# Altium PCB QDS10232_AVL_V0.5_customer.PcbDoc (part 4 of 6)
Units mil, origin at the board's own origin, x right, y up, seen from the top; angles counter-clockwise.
Board outline 3500 x 3799 mil, 6 copper layers (Top Layer, GND, INT1, PWR1, PWR2, Bottom Layer), stack 78.834 mil thick; 254 components, 204 nets, 7039 pads, 595 vias.
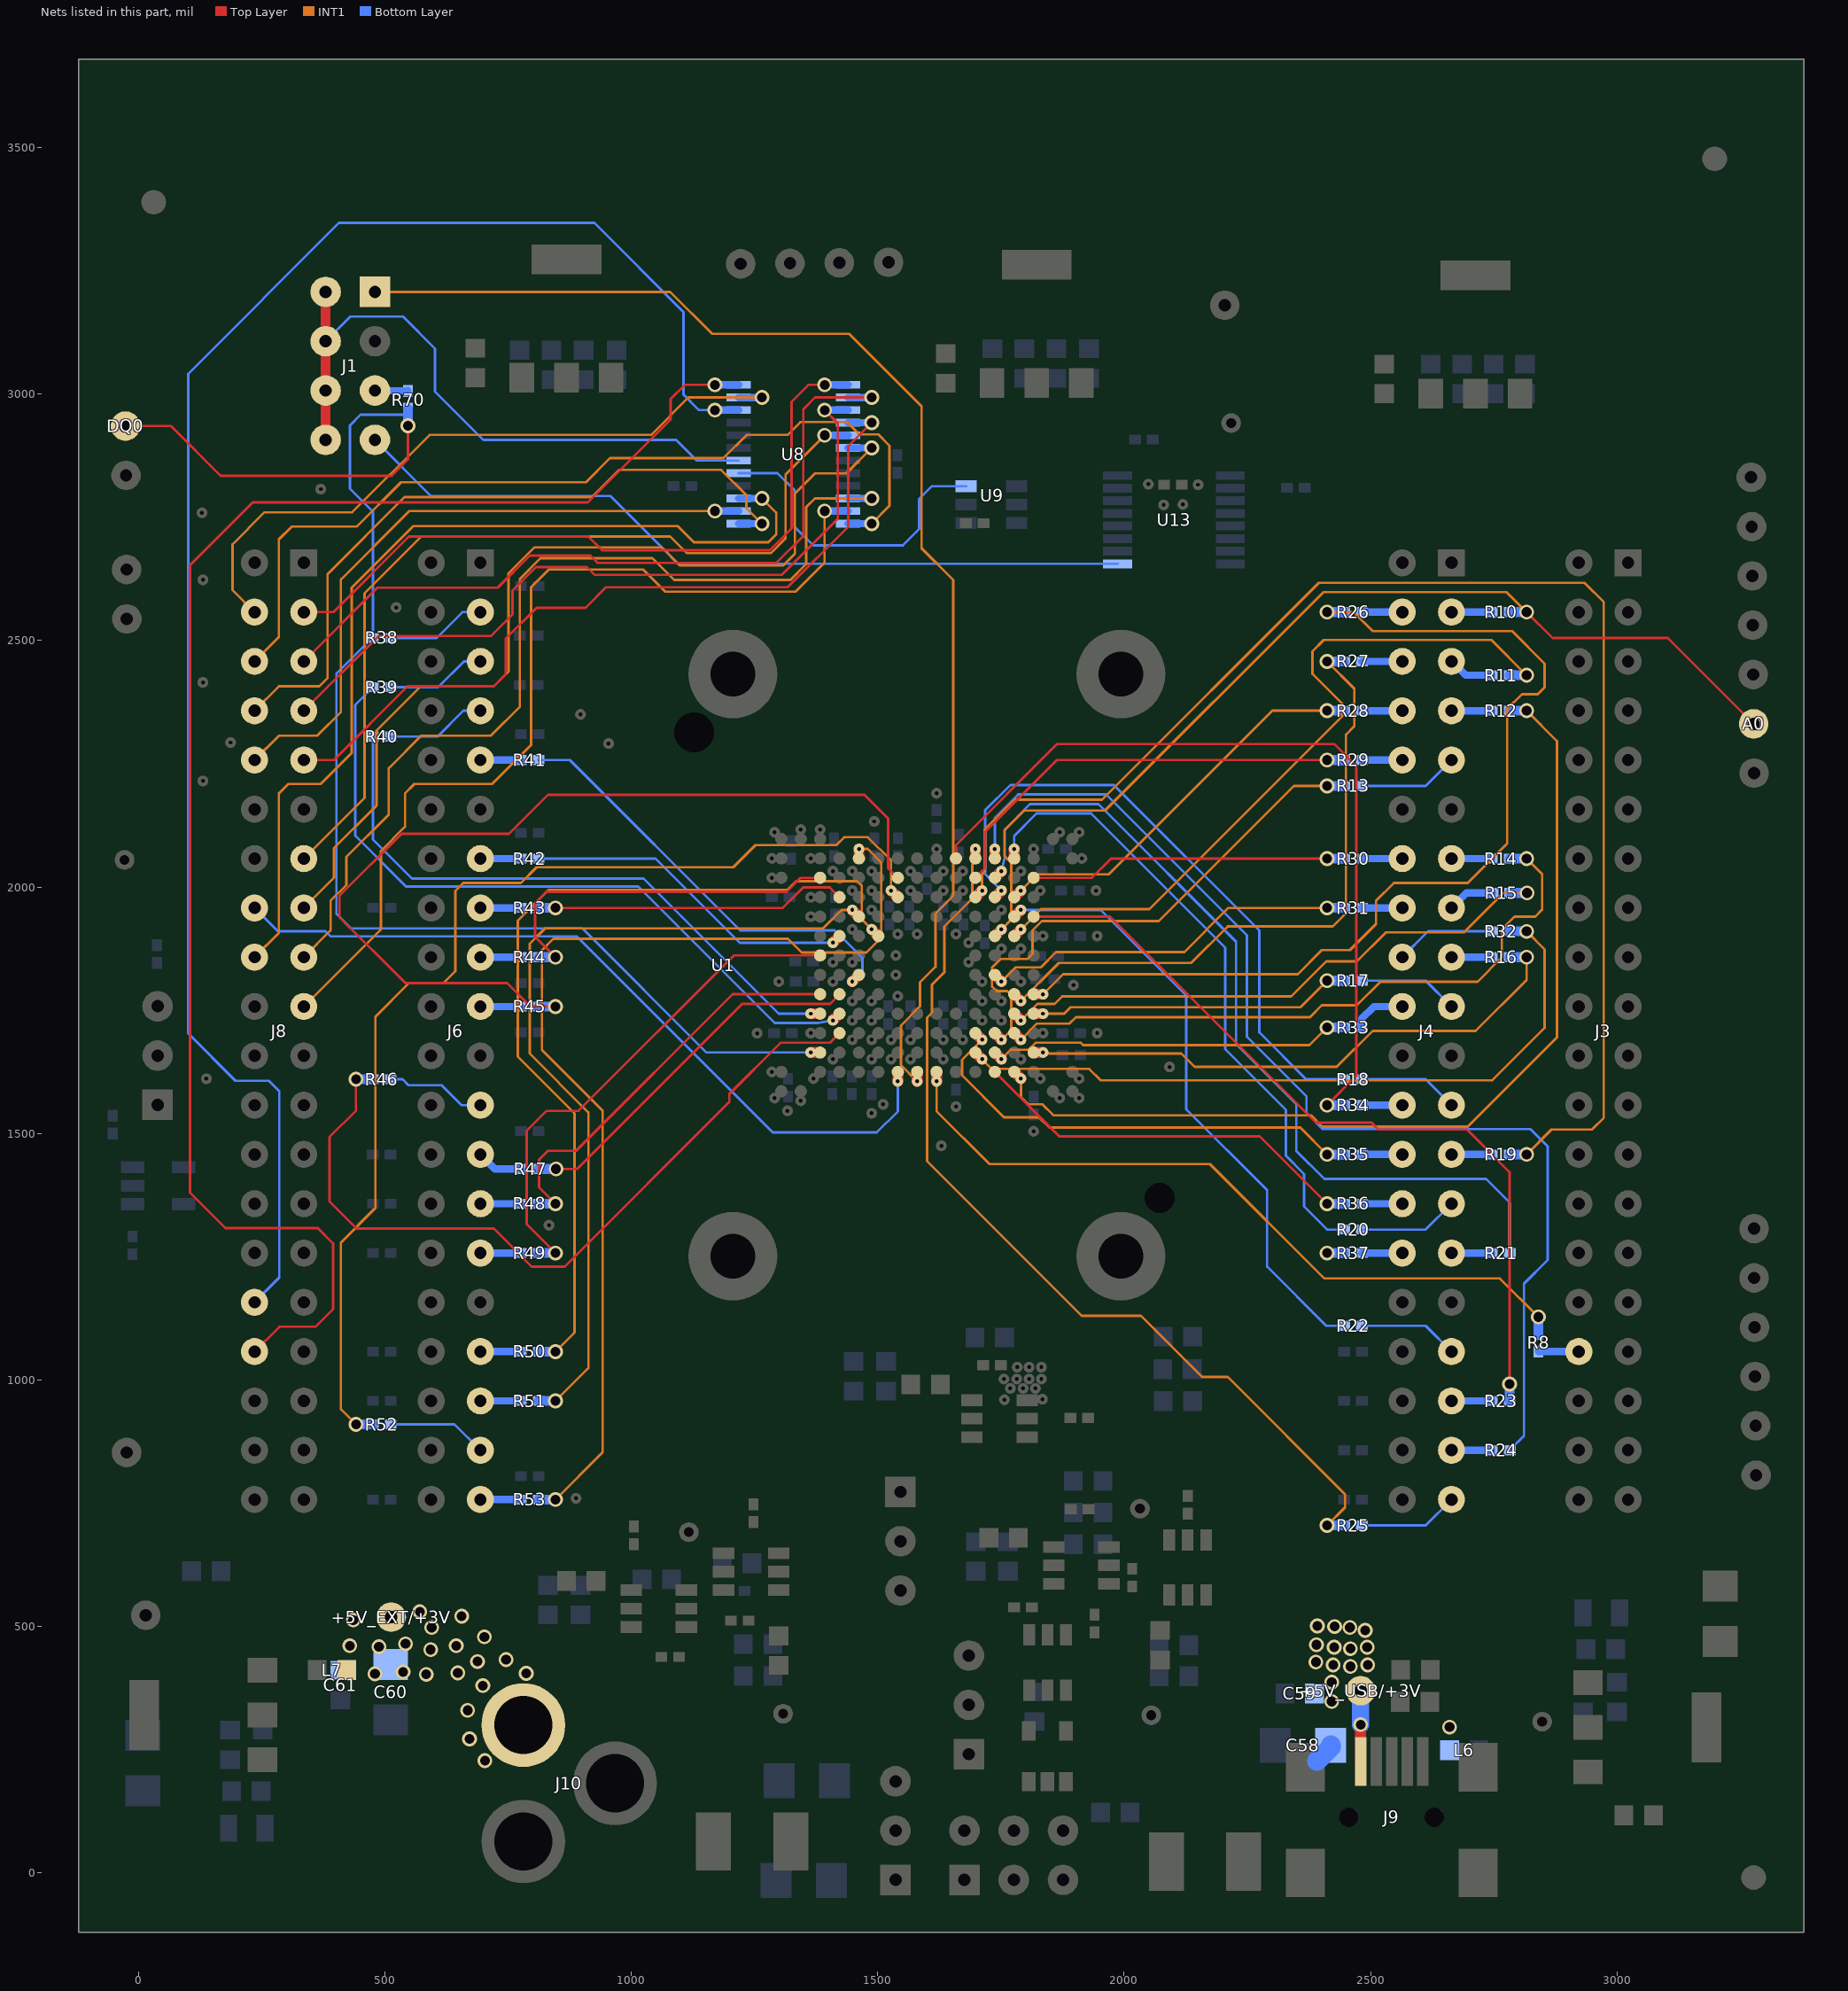
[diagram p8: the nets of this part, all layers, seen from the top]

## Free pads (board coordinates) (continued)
  round 1.28 on Bottom Overlay: ""(2911.56,3465.77) ""(2911.56,3465.77) ""(2911.56,3466.03) ""(2911.56,3467.05) ""(2911.56,3467.37) ""(2911.56,3467.37) ""(2911.56,3465.77) ""(2911.56,3465.77) ""(2911.56,3466.03) ""(2911.56,3467.05) ""(2911.56,3467.37) ""(2911.56,3467.37) ""(2911.98,3468.08) ""(2911.98,3468.08) ""(2912.01,3465) ""(2912.01,3465) ""(2912.59,3469.11) ""(2912.59,3469.11) ""(2912.59,3463.97) ""(2912.59,3463.97) ""(2912.66,3463.86) ""(2912.66,3463.86) ""(2912.66,3463.86) ""(2912.66,3463.86) ""(2913.19,3470.14) ""(2913.19,3470.14) ""(2913.36,3462.94) ""(2913.36,3462.94) ""(2913.79,3471.16) ""(2913.79,3471.16) ""(2914.15,3461.92) ""(2914.15,3461.92) ""(2914.4,3472.19) ""(2914.4,3472.19) ""(2914.93,3460.89) ""(2914.93,3460.89) ""(2915,3473.22) ""(2915,3473.22) ""(2915.16,3534.93) ""(2915.16,3534.93) ""(2915.16,3534.93) ""(2915.16,3534.93) ""(2915.17,3534.88) ""(2915.17,3534.88) ""(2915.25,3535.91) ""(2915.25,3535.91) ""(2915.28,3533.85) ""(2915.28,3533.85) ""(2915.35,3536.93) ""(2915.35,3536.93) ""(2915.39,3532.82) ""(2915.39,3532.82) ""(2915.44,3537.96) ""(2915.45,3537.96) ""(2915.5,3531.8) ""(2915.5,3531.8) ""(2915.54,3538.99) ""(2915.54,3538.99) ""(2915.6,3474.25) ""(2915.6,3474.25) ""(2915.61,3530.77) ""(2915.61,3530.77) ""(2915.64,3540.02) ""(2915.64,3540.02) ""(2915.72,3529.74) ""(2915.72,3459.86) ""(2915.72,3459.86) ""(2915.73,3541.04) ""(2915.73,3541.04) ""(2915.83,3542.07) ""(2915.83,3542.07) ""(2915.83,3528.71) ""(2915.83,3528.71) ""(2915.92,3543.1) ""(2915.92,3543.1) ""(2915.94,3527.69) ""(2915.94,3527.69) ""(2916.02,3544.13) ""(2916.02,3544.13) ""(2916.05,3526.66) ""(2916.05,3526.66) ""(2916.11,3545.16) ""(2916.11,3545.16) ""(2916.12,3526.01) ""(2916.12,3526.01) ""(2916.12,3526.01) ""(2916.12,3526.01) ""(2916.21,3475.28) ""(2916.21,3475.28) ""(2916.21,3546.18) ""(2916.21,3546.18) ""(2916.21,3525.63) ""(2916.21,3525.63) ""(2916.3,3475.44) ""(2916.3,3475.44) ""(2916.3,3475.44) ""(2916.3,3475.44) ""(2916.31,3547.21) ""(2916.31,3547.21) ""(2916.4,3475.28) ""(2916.4,3475.28) ""(2916.4,3548.24) ""(2916.4,3548.24) ""(2916.45,3548.73) ""(2916.45,3548.73) ""(2916.45,3548.73) ""(2916.45,3548.73) ""(2916.47,3524.6) ""(2916.47,3524.6) ""(2916.51,3458.83) ""(2916.51,3458.83) ""(2916.59,3549.27) ""(2916.59,3549.27) ""(2916.73,3523.57) ""(2916.73,3523.57) ""(2916.74,3458.53) ""(2916.74,3458.53) ""(2916.74,3458.53) ""(2916.74,3458.53) ""(2916.85,3550.29) ""(2916.85,3550.29) ""(2916.97,3474.25) ""(2916.97,3474.25) ""(2916.99,3522.55) ""(2917.11,3551.32) ""(2917.11,3551.32) ""(2917.24,3521.52) ""(2917.24,3521.52) ""(2917.38,3552.35) ""(2917.38,3552.35) ""(2917.44,3473.4) ""(2917.44,3473.4) ""(2917.44,3473.4) ""(2917.44,3473.4) ""(2917.5,3520.49) ""(2917.5,3520.49) ""(2917.64,3553.38) ""(2917.64,3553.38) ""(2917.66,3473.22) ""(2917.66,3473.22) ""(2917.74,3457.8) ""(2917.74,3457.8) ""(2917.76,3519.46) ""(2917.76,3519.46) ""(2917.9,3554.4) ""(2917.9,3554.4) ""(2918.01,3518.44) ""(2918.01,3518.44) ""(2918.17,3555.43) ""(2918.17,3555.43) ""(2918.27,3517.41) ""(2918.27,3517.41) ""(2918.43,3556.46) ""(2918.43,3556.46) ""(2918.53,3516.38) ""(2918.53,3516.38) ""(2918.69,3515.73) ""(2918.69,3515.73) ""(2918.69,3515.73) ""(2918.69,3515.73) ""(2918.7,3557.49) ""(2918.7,3557.49) ""(2918.84,3515.35) ""(2918.84,3515.35) ""(2918.89,3472.19) ""(2918.89,3472.19) ""(2918.96,3558.51) ""(2918.96,3558.51) ""(2919.17,3456.78) ""(2919.17,3456.78) ""(2919.22,3559.54) ""(2919.22,3559.54) ""(2919.23,3514.33) ""(2919.23,3514.33) ""(2919.49,3560.57) ""(2919.49,3560.57) ""(2919.63,3513.3) ""(2919.63,3513.3) ""(2919.67,3561.28) ""(2919.67,3561.28) ""(2919.67,3561.28) ""(2919.67,3561.28) ""(2919.67,3471.54) ""(2919.67,3471.54) ""(2919.67,3471.54) ""(2919.67,3471.54) ""(2919.79,3561.6) ""(2919.79,3561.6) ""(2920.02,3512.27) ""(2920.02,3512.27) ""(2920.19,3562.63) ""(2920.19,3562.63) ""(2920.36,3471.16) ""(2920.36,3471.16) ""(2920.42,3511.24) ""(2920.42,3511.24) ""(2920.59,3563.65) ""(2920.59,3563.65) ""(2920.59,3455.75) ""(2920.59,3455.75) ""(2920.81,3510.22) ""(2920.81,3510.22) ""(2920.99,3564.68) ""(2920.99,3564.68) ""(2921.21,3509.19) ""(2921.21,3509.19) ""(2921.38,3565.71) ""(2921.38,3565.71) ""(2921.61,3508.16) ""(2921.61,3508.16) ""(2921.78,3566.74) ""(2921.78,3566.74) ""(2921.91,3507.36) ""(2921.91,3507.36) ""(2921.91,3507.36) ""(2921.91,3507.36) ""(2922.02,3454.72) ""(2922.02,3454.72) ""(2922.02,3507.13) ""(2922.02,3507.13) ""(2922.18,3567.76) ""(2922.18,3567.76) ""(2922.21,3470.14) ""(2922.21,3470.14) ""(2922.38,3454.46) ""(2922.38,3454.46) ""(2922.38,3454.46) ""(2922.38,3454.46) ""(2922.49,3506.1) ""(2922.49,3506.1) ""(2922.58,3568.79) ""(2922.58,3568.79) ""(2922.97,3505.08) ""(2922.97,3505.08) ""(2922.98,3569.82) ""(2922.98,3569.82) ""(2923.01,3469.69) ""(2923.01,3469.69) ""(2923.01,3469.69) ""(2923.01,3469.69) ""(2923.37,3570.85) ""(2923.37,3570.85) ""(2923.44,3504.05) ""(2923.44,3504.05) ""(2923.5,3571.16) ""(2923.5,3571.16) ""(2923.5,3571.16) ""(2923.5,3571.16) ""(2923.91,3453.69) ""(2923.91,3453.69) ""(2923.92,3503.02) ""(2923.92,3503.02) ""(2924.03,3571.87) ""(2924.03,3571.87) ""(2924.39,3501.99) ""(2924.39,3501.99) ""(2924.79,3572.9) ""(2924.79,3572.9) ""(2924.87,3500.97) ""(2924.87,3500.97) ""(2925.34,3499.94) ""(2925.34,3499.94) ""(2925.55,3573.93) ""(2925.55,3573.93) ""(2925.75,3499.06) ""(2925.75,3499.06) ""(2925.75,3499.06) ""(2925.75,3499.06) ""(2925.87,3498.91) ""(2925.87,3498.91) ""(2925.97,3452.67) ""(2925.97,3452.67) ""(2926.31,3574.96) ""(2926.31,3574.96) ""(2926.34,3469.69) ""(2926.34,3469.69) ""(2926.34,3469.69) ""(2926.34,3469.69) ""(2926.69,3497.88) ""(2926.69,3497.88) ""(2927.07,3575.99) ""(2927.07,3575.99) ""(2927.51,3496.86) ""(2927.51,3496.86) ""(2927.83,3577.01) ""(2927.84,3577.01) ""(2928.03,3451.64) ""(2928.03,3451.64) ""(2928.34,3495.83) ""(2928.34,3495.83) ""(2928.6,3578.04) ""(2928.6,3578.04) ""(2929.16,3494.8) ""(2929.16,3494.8) ""(2929.33,3450.99) ""(2929.33,3450.99) ""(2929.33,3450.99) ""(2929.33,3450.99) ""(2929.36,3579.07) ""(2929.36,3579.07) ""(2929.87,3579.75) ""(2929.87,3579.75) ""(2929.87,3579.75) ""(2929.87,3579.75) ""(2929.98,3493.77) ""(2929.98,3493.77) ""(2930.18,3470.04) ""(2930.18,3470.04) ""(2930.18,3470.04) ""(2930.18,3470.04) ""(2930.21,3580.1) ""(2930.21,3580.1) ""(2930.41,3470.14) ""(2930.41,3470.14) ""(2930.81,3492.75) ""(2930.81,3492.75) ""(2930.93,3450.61) ""(2930.93,3450.61) ""(2931.24,3581.12) ""(2931.24,3581.12) ""(2931.63,3491.72) ""(2931.63,3491.72) ""(2932.08,3491.15) ""(2932.08,3491.15) ""(2932.08,3491.15) ""(2932.08,3491.15) ""(2932.27,3582.15) ""(2932.27,3582.15) ""(2932.68,3490.69) ""(2932.68,3490.69) ""(2932.88,3471.16) ""(2932.88,3471.16) ""(2933.3,3583.18) ""(2933.3,3583.18) ""(2934.02,3489.66) ""(2934.02,3489.66) ""(2934.32,3584.21) ""(2934.32,3584.21) ""(2934.37,3471.78) ""(2934.37,3471.78) ""(2934.37,3471.78) ""(2934.37,3471.78) ""(2934.65,3449.74) ""(2934.65,3449.74) ""(2934.65,3449.74) ""(2934.65,3449.74) ""(2935.05,3472.19) ""(2935.05,3472.19) ""(2935.35,3585.23) ""(2935.35,3585.23) ""(2935.36,3488.63) ""(2935.36,3488.63) ""(2936.38,3586.26) ""(2936.38,3586.26) ""(2936.42,3449.58) ""(2936.42,3449.58) ""(2936.69,3487.61) ""(2936.69,3487.61) ""(2936.76,3473.22) ""(2936.76,3473.22) ""(2936.88,3586.76) ""(2936.88,3586.76) ""(2936.88,3586.76) ""(2936.88,3586.76) ""(2937.54,3473.69) ""(2937.54,3473.69) ""(2937.54,3473.69) ""(2937.54,3473.69) ""(2937.75,3587.29) ""(2937.75,3587.29) ""(2938.03,3486.58) ""(2938.03,3486.58) ""(2939.37,3485.55) ""(2939.37,3485.55) ""(2939.44,3588.32) ""(2939.44,3588.32) ""(2939.98,3474.25) ""(2939.98,3474.25) ""(2940.35,3484.79) ""(2940.35,3484.79) ""(2940.35,3484.79) ""(2940.35,3484.79) ""(2940.89,3484.52) ""(2940.89,3484.52) ""(2941.13,3589.34) ""(2941.13,3589.34) ""(2941.54,3474.61) ""(2941.54,3474.61) ""(2941.54,3474.61) ""(2941.54,3474.61) ""(2941.89,3449.11) ""(2941.89,3449.11) ""(2941.89,3449.11) ""(2941.89,3449.11) ""(2942.82,3590.37) ""(2942.82,3590.37) ""(2942.95,3483.5) ""(2942.95,3483.5) ""(2944.19,3591.2) ""(2944.19,3591.2) ""(2944.19,3591.2) ""(2944.19,3591.2) ""(2944.36,3449.58) ""(2944.36,3449.58) ""(2944.61,3591.4) ""(2944.61,3591.4) ""(2945.01,3482.47) ""(2945.01,3482.47) ""(2946.22,3475.28) ""(2946.22,3475.28) ""(2946.84,3592.43) ""(2946.84,3592.43) ""(2947.06,3481.44) ""(2947.06,3481.44) ""(2948.33,3475.58) ""(2948.33,3475.58) ""(2948.33,3475.58) ""(2948.33,3475.58) ""(2948.59,3480.68) ""(2948.59,3480.68) ""(2948.59,3480.68) ""(2948.59,3480.68) ""(2949.07,3593.46) ""(2949.07,3593.46) ""(2949.71,3450.61) ""(2949.71,3450.61) ""(2949.82,3480.41) ""(2949.82,3480.41) ""(2950.11,3450.69) ""(2950.11,3450.69) ""(2950.11,3450.69) ""(2950.11,3450.69) ""(2951.3,3594.48) ""(2951.3,3594.48) ""(2952.48,3595.03) ""(2952.48,3595.03) ""(2952.48,3595.03) ""(2952.48,3595.03) ""(2952.84,3451.64) ""(2952.84,3451.64) ""(2953.9,3476.3) ""(2953.9,3476.3) ""(2954.55,3479.39) ""(2954.55,3479.39) ""(2954.82,3595.51) ""(2954.82,3595.51) ""(2955.67,3528.71) ""(2955.67,3528.71) ""(2955.67,3529.74) ""(2955.67,3529.74) ""(2955.67,3530.77) ""(2955.67,3530.77) ""(2955.67,3531.8) ""(2955.67,3531.8) ""(2955.67,3532.82) ""(2955.67,3532.82) ""(2955.67,3533.85) ""(2955.67,3533.85) ""(2955.67,3534.88) ""(2955.67,3534.88) ""(2955.67,3535.91) ""(2955.67,3535.91) ""(2955.67,3536.93) ""(2955.67,3536.93) ""(2955.67,3537.96) ""(2955.67,3537.96) ""(2955.67,3538.99) ""(2955.67,3538.99) ""(2955.67,3540.02) ""(2955.67,3540.02) ""(2955.67,3541.04) ""(2955.67,3541.04) ""(2955.67,3542.07) ""(2955.67,3542.07) ""(2955.67,3543.1) ""(2955.67,3543.1) ""(2955.67,3544.13) ""(2955.67,3544.13) ""(2955.67,3545.16) ""(2955.67,3545.16) ""(2955.71,3527.69) ""(2955.71,3527.69) ""(2955.73,3546.18) ""(2955.73,3546.18) ""(2955.76,3526.66) ""(2955.76,3526.66) ""(2955.78,3547.21) ""(2955.78,3547.21) ""(2955.8,3452.67) ""(2955.8,3452.67) ""(2955.82,3525.63) ""(2955.82,3525.63) ""(2955.84,3548.24) ""(2955.84,3548.24) ""(2955.88,3524.6) ""(2955.88,3524.6) ""(2955.89,3549.27) ""(2955.89,3549.27) ""(2955.94,3523.57) ""(2955.94,3523.57) ""(2955.94,3550.29) ""(2955.94,3550.29) ""(2955.99,3522.55) ""(2956,3551.32) ""(2956,3551.32) ""(2956.05,3521.52) ""(2956.05,3521.52) ""(2956.05,3552.35) ""(2956.05,3552.35) ""(2956.11,3520.49) ""(2956.11,3553.38) ""(2956.11,3520.49) ""(2956.11,3553.38) ""(2956.16,3554.4) ""(2956.16,3554.4) ""(2956.16,3519.46) ""(2956.16,3519.46) ""(2956.21,3555.43) ""(2956.21,3555.43) ""(2956.22,3518.44) ""(2956.22,3518.44) ""(2956.27,3556.46) ""(2956.27,3556.46) ""(2956.28,3517.41) ""(2956.28,3517.41) ""(2956.32,3557.49) ""(2956.32,3557.49) ""(2956.34,3516.38) ""(2956.34,3516.38) ""(2956.38,3558.51) ""(2956.38,3558.51) ""(2956.39,3515.35) ""(2956.39,3515.35) ""(2956.43,3559.54) ""(2956.43,3559.54) ""(2956.45,3514.33) ""(2956.45,3514.33) ""(2956.49,3560.57) ""(2956.49,3560.57) ""(2956.51,3513.3) ""(2956.51,3513.3) ""(2956.54,3561.6) ""(2956.54,3561.6) ""(2956.56,3512.27) ""(2956.56,3512.27) ""(2956.59,3562.63) ""(2956.59,3562.63) ""(2956.62,3511.24) ""(2956.62,3511.24) ""(2956.65,3563.65) ""(2956.65,3563.65) ""(2956.77,3510.22) ""(2956.77,3510.22) ""(2956.92,3564.68) ""(2956.92,3564.68) ""(2956.99,3509.19) ""(2956.99,3509.19) ""(2957.18,3565.71) ""(2957.18,3565.71) ""(2957.21,3508.16) ""(2957.21,3508.16) ""(2957.36,3453.21) ""(2957.36,3453.21) ""(2957.36,3453.21) ""(2957.36,3453.21) ""(2957.43,3507.13) ""(2957.43,3507.13) ""(2957.44,3566.74) ""(2957.44,3566.74) ""(2957.65,3506.1) ""(2957.65,3506.1) ""(2957.71,3567.76) ""(2957.71,3567.76) ""(2957.87,3505.08) ""(2957.87,3505.08) ""(2957.97,3568.79) ""(2957.97,3568.79) ""(2958.06,3453.69) ""(2958.06,3453.69) ""(2958.09,3504.05) ""(2958.09,3504.05) ""(2958.24,3569.82) ""(2958.24,3569.82) ""(2958.31,3503.02) ""(2958.31,3503.02) ""(2958.5,3570.85) ""(2958.5,3570.85) ""(2958.53,3501.99) ""(2958.53,3501.99) ""(2958.76,3571.87) ""(2958.76,3571.87) ""(2958.82,3500.97) ""(2958.82,3500.97) ""(2959.03,3572.9) ""(2959.03,3572.9) ""(2959.15,3499.94) ""(2959.15,3499.94) ""(2959.28,3478.36) ""(2959.28,3478.36) ""(2959.29,3573.93) ""(2959.29,3573.93) ""(2959.47,3498.91) ""(2959.47,3498.91) ""(2959.53,3454.72) ""(2959.53,3454.72) ""(2959.55,3574.96) ""(2959.55,3574.96) ""(2959.79,3596.54) ""(2959.79,3596.54) ""(2959.79,3497.88) ""(2959.79,3497.88) ""(2959.82,3575.99) ""(2959.82,3575.99) ""(2960.12,3496.86) ""(2960.12,3496.86) ""(2960.32,3577.01) ""(2960.32,3577.01) ""(2960.44,3495.83) ""(2960.44,3495.83) ""(2960.97,3578.04) ""(2960.97,3578.04) ""(2961,3494.8) ""(2961,3494.8) ""(2961,3455.75) ""(2961,3455.75) ""(2961.61,3579.07) ""(2961.61,3579.07) ""(2961.68,3493.77) ""(2961.68,3493.77) ""(2961.72,3596.94) ""(2961.72,3596.94) ""(2961.72,3596.94) ""(2961.72,3596.94) ""(2961.79,3477.33) ""(2961.79,3477.33) ""(2962.25,3580.1) ""(2962.25,3580.1) ""(2962.37,3492.75) ""(2962.37,3492.75) ""(2962.46,3456.78) ""(2962.46,3456.78) ""(2962.9,3581.12) ""(2962.9,3581.12) ""(2963.18,3477.51) ""(2963.18,3477.51) ""(2963.18,3477.51) ""(2963.18,3477.51) ""(2963.42,3491.72) ""(2963.42,3491.72) ""(2963.93,3457.8) ""(2963.93,3457.8) ""(2964.26,3582.15) ""(2964.26,3582.15) ""(2964.57,3490.69) ""(2964.57,3490.69) ""(2965.4,3458.83) ""(2965.4,3458.83) ""(2966.19,3583.18) ""(2966.19,3583.18) ""(2966.41,3489.66) ""(2966.41,3489.66) ""(2966.87,3459.86) ""(2966.87,3459.86) ""(2966.93,3459.9) ""(2966.93,3459.9) ""(2966.93,3459.9) ""(2966.93,3459.9) ""(2967.96,3460.89) ""(2967.96,3460.89) ""(2969.03,3461.92) ""(2969.04,3461.92) ""(2970.11,3462.94) ""(2970.11,3462.94) ""(2970.84,3597.57) ""(2970.84,3597.57) ""(2971.03,3597.58) ""(2971.03,3597.58) ""(2971.03,3597.58) ""(2971.03,3597.58) ""(2971.18,3463.97) ""(2971.18,3463.97) ""(2971.39,3597.57) ""(2971.39,3597.57) ""(2972.26,3465) ""(2972.26,3465) ""(2972.52,3488.63) ""(2972.52,3488.63) ""(2973.09,3488.63) ""(2973.09,3488.63) ""(2973.33,3466.03) ""(2973.33,3466.03) ""(2974.4,3467.05) ""(2974.4,3467.05) ""(2974.68,3467.32) ""(2974.68,3467.32) ""(2974.68,3467.32) ""(2974.68,3467.32) ""(2975.31,3583.18) ""(2975.31,3583.18) ""(2975.4,3468.08) ""(2975.4,3468.08) ""(2975.91,3489.66) ""(2975.91,3489.66) ""(2976.38,3469.11) ""(2976.38,3469.11) ""(2977.27,3582.15) ""(2977.27,3582.15) ""(2977.36,3490.69) ""(2977.36,3490.69) ""(2977.36,3470.14) ""(2977.36,3470.14) ""(2978.02,3581.12) ""(2978.02,3581.12) ""(2978.33,3471.16) ""(2978.33,3471.16) ""(2978.39,3491.72) ""(2978.39,3491.72) ""(2978.77,3580.1) ""(2978.77,3580.1) ""(2979.31,3472.19) ""(2979.31,3472.19) ""(2979.41,3492.75) ""(2979.41,3492.75) ""(2979.52,3579.07) ""(2979.52,3579.07) ""(2979.64,3597.26) ""(2979.64,3597.26) ""(2979.64,3597.26) ""(2979.64,3597.26) ""(2979.87,3493.77) ""(2979.87,3493.77) ""(2980.09,3578.04) ""(2980.09,3578.04) ""(2980.27,3494.8) ""(2980.29,3473.22) ""(2980.29,3473.22) ""(2980.53,3577.01) ""(2980.53,3577.01) ""(2980.68,3495.83) ""(2980.68,3495.83) ""(2980.95,3473.92) ""(2980.95,3473.92) ""(2980.95,3473.92) ""(2980.95,3473.92) ""(2980.97,3575.99) ""(2980.97,3575.99) ""(2981.08,3496.86) ""(2981.08,3496.86) ""(2981.41,3574.96) ""(2981.41,3574.96) ""(2981.43,3474.25) ""(2981.43,3474.25) ""(2981.48,3497.88) ""(2981.48,3497.88) ""(2981.83,3573.93) ""(2981.83,3573.93) ""(2981.88,3498.91) ""(2981.88,3498.91) ""(2982.14,3572.9) ""(2982.14,3572.9) ""(2982.29,3499.94) ""(2982.29,3499.94) ""(2982.32,3596.54) ""(2982.32,3596.54) ""(2982.45,3571.87) ""(2982.45,3571.87) ""(2982.55,3500.97) ""(2982.55,3500.97) ""(2982.73,3501.99) ""(2982.73,3501.99) ""(2982.76,3570.85) ""(2982.76,3570.85) ""(2982.91,3503.02) ""(2982.91,3503.02) ""(2982.92,3475.28) ""(2982.92,3475.28) ""(2982.93,3569.82) ""(2982.93,3569.82) ""(2983.08,3504.05) ""(2983.08,3504.05) ""(2983.09,3568.79) ""(2983.09,3568.79) ""(2983.26,3505.08) ""(2983.26,3505.08) ""(2983.26,3567.76) ""(2983.26,3567.76) ""(2983.43,3566.74) ""(2983.43,3566.74) ""(2983.44,3506.1) ""(2983.44,3506.1) ""(2983.59,3565.71) ""(2983.59,3565.71) ""(2983.61,3507.13) ""(2983.62,3507.13) ""(2983.76,3564.68) ""(2983.76,3564.68) ""(2983.79,3508.16) ""(2983.79,3508.16) ""(2983.92,3563.65) ""(2983.92,3563.65) ""(2983.97,3509.19) ""(2983.97,3509.19) ""(2984.09,3562.63) ""(2984.09,3562.63) ""(2984.12,3510.22) ""(2984.12,3510.22) ""(2984.23,3511.24) ""(2984.23,3511.24) ""(2984.26,3561.6) ""(2984.26,3561.6) ""(2984.34,3512.27) ""(2984.34,3512.27) ""(2984.4,3476.3) ""(2984.4,3476.3) ""(2984.41,3560.57) ""(2984.41,3560.57) ""(2984.46,3513.3) ""(2984.46,3513.3) ""(2984.51,3559.54) ""(2984.51,3559.54) ""(2984.57,3514.33) ""(2984.57,3514.33) ""(2984.61,3558.51) ""(2984.61,3558.51) ""(2984.68,3515.35) ""(2984.68,3515.35) ""(2984.7,3557.49) ""(2984.7,3557.49) ""(2984.79,3516.38) ""(2984.79,3516.38) ""(2984.8,3556.46) ""(2984.8,3556.46) ""(2984.9,3555.43) ""(2984.9,3555.43) ""(2984.9,3517.41) ""(2984.9,3517.41) ""(2984.99,3554.4) ""(2984.99,3554.4) ""(2985.01,3518.44) ""(2985.01,3518.44) ""(2985.09,3553.38) ""(2985.09,3553.38) ""(2985.13,3519.46) ""(2985.13,3519.46) ""(2985.18,3552.35) ""(2985.18,3552.35) ""(2985.24,3520.49) ""(2985.24,3520.49) ""(2985.28,3551.32) ""(2985.28,3551.32) ""(2985.35,3521.52) ""(2985.35,3521.52) ""(2985.38,3550.29) ""(2985.38,3550.29) ""(2985.43,3549.27) ""(2985.43,3549.27) ""(2985.46,3522.55) ""(2985.46,3522.55) ""(2985.48,3548.24) ""(2985.48,3548.24) ""(2985.53,3547.21) ""(2985.53,3547.21) ""(2985.57,3523.57) ""(2985.57,3523.57) ""(2985.59,3546.18) ""(2985.59,3546.18) ""(2985.64,3545.16) ""(2985.64,3545.16) ""(2985.69,3524.6) ""(2985.69,3524.6) ""(2985.69,3544.13) ""(2985.69,3544.13) ""(2985.73,3525.63) ""(2985.73,3525.63) ""(2985.74,3543.1) ""(2985.74,3543.1) ""(2985.76,3526.66) ""(2985.76,3526.66) ""(2985.78,3527.69) ""(2985.78,3527.69) ""(2985.79,3542.07) ""(2985.79,3542.07) ""(2985.81,3528.71) ""(2985.81,3528.71) ""(2985.84,3529.74) ""(2985.84,3529.74) ""(2985.84,3541.04) ""(2985.84,3541.04) ""(2985.86,3530.77) ""(2985.86,3530.77) ""(2985.89,3477.33) ""(2985.89,3477.33) ""(2985.89,3531.8) ""(2985.89,3531.8) ""(2985.89,3540.02) ""(2985.89,3540.02) ""(2985.92,3532.82) ""(2985.92,3532.82) ""(2985.94,3538.99) ""(2985.95,3538.99) ""(2985.95,3533.85) ""(2985.95,3533.85) ""(2985.97,3534.88) ""(2985.97,3534.88) ""(2986,3537.96) ""(2986,3537.96) ""(2986,3535.91) ""(2986,3535.91) ""(2986.03,3536.93) ""(2986.03,3536.93) ""(2986.14,3595.51) ""(2986.14,3595.51) ""(2987.37,3478.36) ""(2987.37,3478.36) ""(2987.91,3595.03) ""(2987.91,3595.03) ""(2987.91,3595.03) ""(2987.91,3595.03) ""(2988.86,3479.39) ""(2988.86,3479.39) ""(2989.29,3594.48) ""(2989.29,3594.48) ""(2989.62,3479.91) ""(2989.62,3479.91) ""(2989.62,3479.91) ""(2989.62,3479.91) ""(2990.62,3480.41) ""(2990.62,3480.41) ""(2991.86,3593.46) ""(2991.86,3593.46) ""(2992.68,3481.44) ""(2992.68,3481.44) ""(2994.32,3592.47) ""(2994.32,3592.47) ""(2994.32,3592.47) ""(2994.32,3592.47) ""(2994.41,3592.43) ""(2994.41,3592.43) ""(2994.74,3482.47) ""(2994.74,3482.47) ""(2996.47,3591.4) ""(2996.47,3591.4) ""(2996.79,3483.5) ""(2996.79,3483.5) ""(2997.5,3483.85) ""(2997.5,3483.85) ""(2997.5,3483.85) ""(2997.5,3483.85) ""(2998.53,3590.37) ""(2998.53,3590.37) ""(2998.66,3484.52) ""(2998.66,3484.52) ""(3000.06,3589.6) ""(3000.06,3589.6) ""(3000.06,3589.6) ""(3000.06,3589.6) ""(3000.42,3485.55) ""(3000.42,3485.55) ""(3000.43,3589.34) ""(3000.43,3589.34) ""(3001.87,3588.32) ""(3001.87,3588.32) ""(3002.18,3486.58) ""(3002.18,3486.58) ""(3003.31,3587.29) ""(3003.31,3587.29) ""(3003.95,3487.61) ""(3003.95,3487.61) ""(3004.75,3586.26) ""(3004.75,3586.26) ""(3005.21,3488.34) ""(3005.21,3488.34) ""(3005.21,3488.34) ""(3005.21,3488.34) ""(3005.56,3488.63) ""(3005.56,3488.63) ""(3006.19,3585.23) ""(3006.19,3585.23) ""(3006.75,3584.83) ""(3006.75,3584.83) ""(3006.75,3584.83) ""(3006.75,3584.83) ""(3006.8,3489.66) ""(3006.8,3489.66) ""(3007.38,3584.21) ""(3007.38,3584.21) ""(3008.03,3490.69) ""(3008.03,3490.69) ""(3008.41,3583.18) ""(3008.41,3583.18) ""(3009.26,3491.72) ""(3009.26,3491.72) ""(3009.44,3582.15) ""(3009.44,3582.15) ""(3010.46,3581.12) ""(3010.46,3581.12) ""(3010.5,3492.75) ""(3010.5,3492.75) ""(3010.88,3493.06) ""(3010.88,3493.06) ""(3010.88,3493.06) ""(3010.88,3493.06) ""(3011.37,3493.77) ""(3011.37,3493.77) ""(3011.49,3580.1) ""(3011.49,3580.1) ""(3012.09,3494.8) ""(3012.09,3494.8) ""(3012.52,3579.07) ""(3012.52,3579.07) ""(3012.8,3495.83) ""(3012.8,3495.83) ""(3012.82,3578.77) ""(3012.82,3578.77) ""(3012.82,3578.77) ""(3012.82,3578.77) ""(3013.38,3578.04) ""(3013.38,3578.04) ""(3013.52,3496.86) ""(3013.52,3496.86) ""(3014.16,3577.01) ""(3014.16,3577.01) ""(3014.23,3497.88) ""(3014.23,3497.88) ""(3014.95,3498.91) ""(3014.95,3498.91) ""(3014.95,3575.99) ""(3014.95,3575.99) ""(3015.66,3499.94) ""(3015.66,3499.94) ""(3015.74,3574.96) ""(3015.74,3574.96) ""(3015.98,3500.38) ""(3015.98,3500.38) ""(3015.98,3500.38) ""(3015.98,3500.38) ""(3016.32,3500.97) ""(3016.32,3500.97) ""(3016.52,3573.93) ""(3016.52,3573.93) ""(3016.94,3573.39) ""(3016.94,3573.39) ""(3016.94,3573.39) ""(3016.94,3573.39) ""(3016.94,3501.99) ""(3016.94,3501.99) ""(3017.18,3572.9) ""(3017.18,3572.9) ""(3017.56,3503.02) ""(3017.56,3503.02) ""(3017.7,3571.87) ""(3017.7,3571.87) ""(3018.18,3504.05) ""(3018.18,3504.05) ""(3018.21,3570.85) ""(3018.21,3570.85) ""(3018.73,3569.82) ""(3018.73,3569.82) ""(3018.79,3505.08) ""(3018.79,3505.08) ""(3018.83,3505.14) ""(3018.83,3505.14) ""(3018.83,3505.14) ""(3018.83,3505.14) ""(3019.2,3506.1) ""(3019.2,3506.1) ""(3019.24,3568.79) ""(3019.24,3568.79) ""(3019.59,3507.13) ""(3019.59,3507.13) ""(3019.75,3567.76) ""(3019.75,3567.76) ""(3019.98,3508.16) ""(3019.98,3508.16) ""(3020.27,3566.74) ""(3020.27,3566.74) ""(3020.37,3509.19) ""(3020.37,3509.19) ""(3020.43,3566.42) ""(3020.43,3566.42) ""(3020.43,3566.42) ""(3020.43,3566.42) ""(3020.64,3565.71) ""(3020.64,3565.71) ""(3020.76,3510.22) ""(3020.76,3510.22) ""(3020.95,3564.68) ""(3020.95,3564.68) ""(3021.15,3511.24) ""(3021.15,3511.24) ""(3021.26,3563.65) ""(3021.26,3563.65) ""(3021.54,3512.27) ""(3021.54,3512.27) ""(3021.57,3562.63) ""(3021.57,3562.63) ""(3021.87,3561.6) ""(3021.87,3561.6) ""(3021.93,3513.3) ""(3021.93,3513.3) ""(3022.18,3560.57) ""(3022.18,3560.57) ""(3022.32,3514.33) ""(3022.32,3514.33) ""(3022.35,3514.4) ""(3022.35,3514.4) ""(3022.35,3514.4) ""(3022.35,3514.4) ""(3022.49,3559.54) ""(3022.49,3559.54) ""(3022.54,3515.35) ""(3022.54,3515.35) ""(3022.74,3516.38) ""(3022.74,3516.38) ""(3022.8,3558.51) ""(3022.8,3558.51) ""(3022.95,3517.41) ""(3022.95,3517.41) ""(3023.11,3557.49) ""(3023.11,3557.49) ""(3023.16,3518.44) ""(3023.16,3518.44) ""(3023.33,3556.77) ""(3023.33,3556.77) ""(3023.33,3556.77) ""(3023.33,3556.77) ""(3023.36,3519.46) ""(3023.36,3519.46) ""(3023.4,3556.46) ""(3023.4,3556.46) ""(3023.57,3520.49) ""(3023.57,3520.49) ""(3023.66,3555.43) ""(3023.66,3555.43) ""(3023.77,3521.52) ""(3023.77,3521.52) ""(3023.92,3554.4) ""(3023.92,3554.4) ""(3023.95,3522.42) ""(3023.95,3522.42) ""(3023.95,3522.42) ""(3023.95,3522.42) ""(3023.97,3522.55) ""(3023.97,3522.55) ""(3024.12,3523.57) ""(3024.12,3523.57) ""(3024.17,3553.38) ""(3024.17,3553.38) ""(3024.28,3524.6) ""(3024.28,3524.6) ""(3024.43,3525.63) ""(3024.43,3525.63) ""(3024.43,3552.35) ""(3024.43,3552.35) ""(3024.58,3526.66) ""(3024.58,3526.66) ""(3024.6,3551.66) ""(3024.6,3551.66) ""(3024.6,3551.66) ""(3024.6,3551.66) ""(3024.64,3551.32) ""(3024.64,3551.32) ""(3024.73,3527.69) ""(3024.73,3527.69) ""(3024.74,3550.29) ""(3024.74,3550.29) ""(3024.85,3549.27) ""(3024.85,3549.27) ""(3024.89,3528.71) ""(3024.89,3528.71) ""(3024.96,3548.24) ""(3024.96,3548.24) ""(3025.04,3529.74) ""(3025.04,3529.74) ""(3025.06,3547.21) ""(3025.06,3547.21) ""(3025.17,3546.18) ""(3025.17,3546.18) ""(3025.19,3530.77) ""(3025.19,3530.77) ""(3025.24,3531.12) ""(3025.24,3531.12) ""(3025.24,3531.12) ""(3025.24,3531.12) ""(3025.26,3531.8) ""(3025.26,3531.8) ""(3025.28,3545.16) ""(3025.28,3545.16) ""(3025.29,3532.82) ""(3025.29,3532.82) ""(3025.32,3533.85) ""(3025.32,3533.85) ""(3025.35,3534.88) ""(3025.35,3534.88) ""(3025.38,3535.91) ""(3025.38,3535.91) ""(3025.38,3544.13) ""(3025.38,3544.13) ""(3025.41,3536.93) ""(3025.41,3536.93) ""(3025.44,3537.96) ""(3025.44,3537.96) ""(3025.47,3538.99) ""(3025.47,3538.99) ""(3025.49,3543.1) ""(3025.49,3543.1) ""(3025.5,3540.02) ""(3025.5,3540.02) ""(3025.53,3541.04) ""(3025.53,3541.04) ""(3025.56,3542.07) ""(3025.56,3542.07) ""(3025.56,3542.38) ""(3025.56,3542.38) ""(3025.56,3542.38) ""(3025.56,3542.38)
  round 1.29 on Bottom Overlay: ""(2915.72,3529.74) ""(2916.99,3522.55) ""(2955.99,3522.55) ""(2980.27,3494.8)
  round 1.8 on Bottom Overlay: ""(2955.67,3528.4) ""(2955.67,3528.4) ""(2955.67,3545.03) ""(2955.67,3545.03) ""(2956.65,3510.78) ""(2956.65,3510.78) ""(2956.65,3563.63) ""(2956.65,3563.63) ""(2956.65,3510.78) ""(2956.65,3510.78) ""(2956.65,3563.63) ""(2956.65,3563.63) ""(2958.61,3501.64) ""(2958.61,3501.64) ""(2958.61,3501.64) ""(2958.61,3501.64) ""(2959.91,3576.35) ""(2959.91,3576.35) ""(2959.91,3576.35) ""(2959.91,3576.35) ""(2960.57,3495.44) ""(2960.57,3495.44) ""(2960.57,3495.44) ""(2960.57,3495.44) ""(2962.52,3492.51) ""(2962.52,3492.51) ""(2963.18,3581.57) ""(2963.18,3581.57) ""(2963.18,3581.57) ""(2963.18,3581.57) ""(2968.08,3584.18) ""(2968.08,3584.18) ""(2968.08,3584.18) ""(2968.08,3584.18) ""(2969.38,3488.92) ""(2969.38,3488.92) ""(2969.38,3488.92) ""(2969.38,3488.92) ""(2972.97,3488.59) ""(2972.97,3488.59) ""(2972.97,3488.59) ""(2972.97,3488.59) ""(2973.3,3584.18) ""(2973.3,3584.18) ""(2973.3,3584.18) ""(2973.3,3584.18) ""(2976.57,3489.9) ""(2976.57,3489.9) ""(2977.22,3582.23) ""(2977.22,3582.23) ""(2977.22,3582.23) ""(2977.22,3582.23) ""(2979.83,3578.64) ""(2979.83,3578.64) ""(2981.79,3574.07) ""(2981.79,3574.07) ""(2981.79,3574.07) ""(2981.79,3574.07) ""(2982.44,3500.34) ""(2982.44,3500.34) ""(2982.44,3500.34) ""(2982.44,3500.34) ""(2985.71,3524.81) ""(2985.71,3524.81) ""(2986.03,3537.2) ""(2986.03,3537.2) ""(2986.03,3537.2) ""(2986.03,3537.2)

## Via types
v1: diameter 30, hole 20, Top Layer to Bottom Layer, 595 vias

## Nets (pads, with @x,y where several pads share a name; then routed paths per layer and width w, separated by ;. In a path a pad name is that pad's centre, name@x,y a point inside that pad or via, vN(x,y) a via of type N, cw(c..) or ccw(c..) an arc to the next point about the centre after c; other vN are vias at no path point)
+5V_EXT/(+3): +5V_EXT/+3V.1 C60.1 C61.1 J10.PWR L7.1
  other v1: 703,228 672,272 668,330 699,380 584,403 480,404 787,405 648,406 537,408 688,429 746,433 593,453 488,459 429,461 645,461 542,465 702,479 595,498 436,513 656,521 571,530
+5V_USB/(+3): +5V_USB/+3V.1 C58.1 C59.1 J9.1 L6.1 | length 186.9
  Top Layer w22: J9.1@2479.62,226.39 v1(2479.62,301)
  Bottom Layer w35: v1(2479.62,301) +5V_USB/+3V.1@2479.62,369.62
  Bottom Layer w40: C58.1@2391,226.96 2419.1,255.06 C58.1@2419.1,259
  other v1: 2660,296 2421,348 2421,387 2459,419 2424,422 2494,422 2389,428 2459,455 2426,458 2493,458 2390,463 2489,492 2458,498 2427,500 2392,501
A0: A0.1 pad.@1751.06,1914.07 R10.2 U1.M9 | length 2099.2
  Top Layer w5: v1(2816.44,2557.56) 2869,2505 3103,2505 A0.1@3277,2331
  Top Layer w22: U1.M9@1737.5,1900.5 pad.@1751.06,1914.07
  INT1 w5: pad.@1751.06,1914.07 1771,1934.01 1771,2049 1757,2063 1757,2115 1797,2155 1961,2155 2404,2598 2776,2598 v1(2816.44,2557.56)
  Bottom Layer w20: R10.2@2782.04,2557.56 v1(2816.44,2557.56)
A0_1: J4.3 R10.1 | length 82
  Bottom Layer w15: J4.3@2664.04,2557.56 R10.1@2746.04,2557.56
A1: pad.@1790.43,1914.07 R11.2 U1.N9 | length 1514.4
  Top Layer w22: U1.N9@1776.87,1900.5 pad.@1790.43,1914.07
  INT1 w5: pad.@1790.43,1914.07 1831.36,1955 2051,1955 2442,2346 2442,2372 2382,2432 2382,2478 2405,2501 2744.92,2501 v1(2816.36,2429.56)
  Bottom Layer w20: R11.2@2781.96,2429.56 v1(2816.36,2429.56)
A1_1: J4.5 R11.1 | length 93.5
  Bottom Layer w15: J4.5@2664.04,2457.56 2664.83,2457.56 2692.83,2429.56 R11.1@2745.96,2429.56
A2: pad.@1790.43,1611.35 R12.2 U1.N2 | length 1966.6
  Top Layer w22: U1.N2@1776.87,1624.91 pad.@1790.43,1611.35
  INT1 w5: pad.@1790.43,1611.35 1790.43,1573.57 1804.63,1559.37 1833.63,1559.37 1856,1537 2379,1537 2402,1514 2697,1514 2878,1695 2878,2296 v1(2816.44,2357.56)
  Bottom Layer w20: R12.2@2782.04,2357.56 v1(2816.44,2357.56)
A2_1: J4.7 R12.1 | length 82
  Bottom Layer w15: J4.7@2664.04,2357.56 R12.1@2746.04,2357.56
A3: pad.@1751.06,1690.09 R13.2 U1.M4 | length 1098
  Top Layer w22: U1.M4@1737.5,1703.65 pad.@1751.06,1690.09
  INT1 w5: pad.@1751.06,1690.09 1771,1710.02 1771,1781 1763,1789 1741,1789 1732,1798 1732,1837 1749,1854 1804,1854 1814,1864 1814,1912 1833,1931 2070,1931 2344.12,2205.12 v1(2411.6,2205.12)
  Bottom Layer w20: v1(2411.6,2205.12) R13.2@2446,2205.12
A3_1: J4.9 R13.1 | length 203.8
  Bottom Layer w5: R13.1@2482,2205.12 2611.6,2205.12 J4.9@2664.04,2257.56
A4: pad.@1790.43,1690.09 R14.2 U1.N4 | length 1370.5
  Top Layer w22: U1.N4@1776.87,1703.65 pad.@1790.43,1690.09
  INT1 w5: pad.@1790.43,1690.09 1823.35,1723 1889,1723 1902,1736 2377,1736 2401,1760 2472,1760 2520,1808 2717,1808 2766,1857 2766,1914 2792,1940 2834,1940 2848,1954 2848,2026 v1(2816.44,2057.56)
  Bottom Layer w20: R14.2@2782.04,2057.56 v1(2816.44,2057.56)
A4_1: J4.13 R14.1 | length 82
  Bottom Layer w15: J4.13@2664.04,2057.56 R14.1@2746.04,2057.56
A5: pad.@1790.43,1729.46 R15.2 U1.N5 | length 1187.6
  Top Layer w22: U1.N5@1776.87,1743.02 pad.@1790.43,1729.46
  INT1 w5: pad.@1790.43,1729.46 1823.98,1763 1859,1763 1874,1778 2339,1778 2410,1849 2472,1849 2531,1908 2689,1908 2769,1988 v1(2817.4,1988)
  Bottom Layer w20: R15.2@2783,1988 v1(2817.4,1988)
A5_1: J4.15 R15.1 | length 95.6
  Bottom Layer w15: J4.15@2664.04,1957.56 2694.48,1988 R15.1@2747,1988
A6: pad.@1835.42,1664.28 R16.2 U1.P3 | length 1165.9
  Top Layer w22: U1.P3@1816.24,1664.28 pad.@1835.42,1664.28
  INT1 w5: pad.@1835.42,1664.28 1837.71,1662 2116,1662 2143,1635 2431,1635 2504,1708 2713,1708 2816.44,1811.44 v1(2816.44,1857.56)
  Bottom Layer w20: R16.2@2782.04,1857.56 v1(2816.44,1857.56)
A6_1: J4.17 R16.1 | length 82
  Bottom Layer w15: J4.17@2664.04,1857.56 R16.1@2746.04,1857.56
A7: pad.@1835.42,1743.02 R17.2 U1.P5 | length 657.5
  Top Layer w22: U1.P5@1816.24,1743.02 pad.@1835.42,1743.02
  INT1 w5: pad.@1835.42,1743.02 1878.23,1743.02 1891.2,1756 2357.6,1756 v1(2411.6,1810)
  Bottom Layer w20: v1(2411.6,1810) R17.2@2446,1810
A7_1: J4.19 R17.1 | length 203.8
  Bottom Layer w5: R17.1@2482,1810 2611.6,1810 J4.19@2664.04,1757.56
A8: pad.@1751.06,1992.81 R18.2 U1.M11 | length 1313.7
  Top Layer w22: U1.M11@1737.5,1979.24 pad.@1751.06,1992.81
  Bottom Layer w5: pad.@1751.06,1992.81 1718,2025.88 1718,2156 1769,2207 1979,2207 2274,1912 2274,1705 2369,1610 R18.2@2446,1610
A8_1: J4.23 R18.1 | length 203.8
  Bottom Layer w5: R18.1@2482,1610 2611.6,1610 J4.23@2664.04,1557.56
A9: pad.@1711.69,1992.81 R19.2 U1.L11 | length 2892.6
  Top Layer w22: U1.L11@1698.13,1979.24 pad.@1711.69,1992.81
  INT1 w5: pad.@1711.69,1992.81 1711.69,2025.69 1717,2031 1717,2117 1777,2177 1955,2177 2395,2617 2934,2617 2973,2578 2973,1532 2949,1508 2866.88,1508 v1(2816.44,1457.56)
  Bottom Layer w20: R19.2@2782.04,1457.56 v1(2816.44,1457.56)
A9_1: J4.25 R19.1 | length 82
  Bottom Layer w15: J4.25@2664.04,1457.56 R19.1@2746.04,1457.56
A10: pad.@1776.87,2077.17 R20.2 U1.N13 | length 1297.1
  Top Layer w22: U1.N13@1776.87,2057.98 pad.@1776.87,2077.17
  Bottom Layer w5: pad.@1776.87,2077.17 1776.87,2103.87 1822,2149 1933,2149 2205,1877 2205,1671 2328,1548 2328,1455 2365,1418 2365,1352 2411.88,1305.12 R20.2@2446,1305.12
A10_1: J4.27 R20.1 | length 203.8
  Bottom Layer w5: R20.1@2482,1305.12 2611.6,1305.12 J4.27@2664.04,1357.56
A11: pad.@1751.06,2032.18 R21.2 U1.M12 | length 1764
  Top Layer w22: U1.M12@1737.5,2018.61 pad.@1751.06,2032.18
  Bottom Layer w5: pad.@1751.06,2032.18 1758,2061 1758,2117 1809,2168 1948,2168 2227,1889 2227,1682 2349,1560 2349,1465 2406,1408 2734,1408 2782.04,1359.96 R21.2@2782.04,1257.56
A11_1: J4.29 R21.1 | length 82
  Bottom Layer w15: J4.29@2664.04,1257.56 R21.1@2746.04,1257.56
A12: pad.@1790.43,1953.44 R22.2 U1.N10 | length 1250.2
  Top Layer w22: U1.N10@1776.87,1939.87 pad.@1790.43,1953.44
  Bottom Layer w5: pad.@1790.43,1953.44 1952.56,1953.44 2126,1780 2126,1549 2290,1385 2290,1230 2410,1110 R22.2@2446,1110
A12_1: J4.33 R22.1 | length 203.8
  Bottom Layer w5: R22.1@2482,1110 2611.6,1110 J4.33@2664.04,1057.56
A13: R23.2 U1.P10 | length 1644.4
  Top Layer w5: U1.P10@1816.24,1939.87 1971.13,1939.87 2389,1522 2502,1522 2516,1508 2695.6,1508 2782,1421.6 v1@2782,992
  Bottom Layer w20: R23.2@2782.04,957.56 v1(2782.04,991.96)
A13_1: J4.35 R23.1 | length 82
  Bottom Layer w15: J4.35@2664.04,957.56 R23.1@2746.04,957.56
A14: pad.@1737.5,2077.17 R24.2 U1.M13 | length 2307.8
  Top Layer w22: U1.M13@1737.5,2057.98 pad.@1737.5,2077.17
  Bottom Layer w5: pad.@1737.5,2077.17 1737.5,2140.5 1785,2188 1963,2188 2249,1902 2249,1696 2370,1575 2370,1542 2403,1509 2824,1509 2859,1474 2859,1243.3 2811,1195.3 2811,886.52 R24.2@2782.04,857.56
A14_1: J4.37 R24.1 | length 82
  Bottom Layer w15: J4.37@2664.04,857.56 R24.1@2746.04,857.56
A15: pad.@1698.13,2077.17 R25.2 U1.L13 | length 1933.4
  Top Layer w22: U1.L13@1698.13,2057.98 pad.@1698.13,2077.17
  INT1 w5: pad.@1698.13,2077.17 1698.13,2051.13 1692,2045 1692,1977 1635,1920 1635,1827 1610,1802 1610,1745 1600,1735 1600,1444 1914,1130 2034,1130 2158,1006 2210,1006 2448,768 2448,741.52 v1(2411.6,705.12)
  Bottom Layer w20: v1(2411.6,705.12) R25.2@2446,705.12
A15_1: J4.39 R25.1 | length 203.8
  Bottom Layer w5: R25.1@2482,705.12 2611.6,705.12 J4.39@2664.04,757.56
A16: pad.@1835.42,1782.39 R26.2 U1.P6 | length 2049.2
  Top Layer w22: U1.P6@1816.24,1782.39 pad.@1835.42,1782.39
  INT1 w5: pad.@1835.42,1782.39 1876.03,1823 2352,1823 2401,1872 2458,1872 2511,1925 2511,1972 2547,2008 2697,2008 2777,2088 2777,2361 2807,2391 2839,2391 2853,2405 2853,2453 2787,2519 2504,2519 2465.44,2557.56 v1(2411.64,2557.56)
  Bottom Layer w20: v1(2411.64,2557.56) R26.2@2446.04,2557.56
A16_1: J4.4 R26.1 | length 82
  Bottom Layer w15: R26.1@2482.04,2557.56 J4.4@2564.04,2557.56
A17: pad.@1790.43,1768.83 R27.2 U1.N6 | length 1327.5
  Top Layer w22: U1.N6@1776.87,1782.39 pad.@1790.43,1768.83
  INT1 w5: pad.@1790.43,1768.83 1867.61,1846 2136,1846 2210,1920 2423,1920 2450,1947 2450,2309 2467,2326 2467,2402.2 v1(2411.64,2457.56)
  Bottom Layer w20: v1(2411.64,2457.56) R27.2@2446.04,2457.56
A17_1: J4.6 R27.1 | length 82
  Bottom Layer w15: R27.1@2482.04,2457.56 J4.6@2564.04,2457.56
A18: pad.@1790.43,1992.81 R28.2 U1.N11 | length 825.9
  Top Layer w22: U1.N11@1776.87,1979.24 pad.@1790.43,1992.81
  INT1 w5: pad.@1790.43,1992.81 1823.31,2025.69 1968.69,2025.69 2300.56,2357.56 v1(2411.64,2357.56)
  Bottom Layer w20: v1(2411.64,2357.56) R28.2@2446.04,2357.56
A18_1: J4.8 R28.1 | length 82
  Bottom Layer w15: R28.1@2482.04,2357.56 J4.8@2564.04,2357.56
A19: R29.2 U1.L12 | length 889.9
  Top Layer w5: U1.L12@1698.13,2018.61 1718,2038.49 1718,2112 1863.56,2257.56 v1(2411.64,2257.56)
  Bottom Layer w20: v1(2411.64,2257.56) R29.2@2446.04,2257.56
A19_1: J4.10 R29.1 | length 82
  Bottom Layer w15: R29.1@2482.04,2257.56 J4.10@2564.04,2257.56
A20: R30.2 U1.P12 | length 645.9
  Top Layer w5: U1.P12@1816.24,2018.61 1934.61,2018.61 1973.56,2057.56 v1(2411.64,2057.56)
  Bottom Layer w20: v1(2411.64,2057.56) R30.2@2446.04,2057.56
A20_1: J4.14 R30.1 | length 82
  Bottom Layer w15: R30.1@2482.04,2057.56 J4.14@2564.04,2057.56
A21: pad.@1751.06,1808.2 R31.2 U1.M7 | length 776
  Top Layer w22: U1.M7@1737.5,1821.76 pad.@1751.06,1808.2
  INT1 w5: pad.@1751.06,1808.2 1779.87,1837 1831,1837 1862,1868 2122,1868 2211.56,1957.56 v1(2411.64,1957.56)
  Bottom Layer w20: v1(2411.64,1957.56) R31.2@2446.04,1957.56
A21_1: J4.16 R31.1 | length 82
  Bottom Layer w15: R31.1@2482.04,1957.56 J4.16@2564.04,1957.56
A22: pad.@1711.69,1650.72 R32.2 U1.L3 | length 1467.6
  Top Layer w22: U1.L3@1698.13,1664.28 pad.@1711.69,1650.72
  INT1 w5: pad.@1711.69,1650.72 1731.41,1631 1929,1631 1952,1608 2747,1608 2853,1714 2853,1873.48 v1(2816.48,1910)
  Bottom Layer w20: R32.2@2782.08,1910 v1(2816.48,1910)
A22_1: J4.18 R32.1 | length 203.8
  Bottom Layer w5: J4.18@2564.04,1857.56 2616.48,1910 R32.1@2746.08,1910
A23: pad.@1751.06,1650.72 R33.2 U1.M3 | length 744.9
  Top Layer w22: U1.M3@1737.5,1664.28 pad.@1751.06,1650.72
  INT1 w5: pad.@1751.06,1650.72 1770.35,1670 1806,1670 1820,1684 1912,1684 1917,1679 2375.6,1679 v1(2411.6,1715)
  Bottom Layer w20: v1(2411.6,1715) R33.2@2446,1715
A23_1: J4.20 R33.1 | length 115.7
  Bottom Layer w15: R33.1@2486.5,1717.5 2484,1715 R33.1@2482,1715 2482,1733 2506.56,1757.56 J4.20@2564.04,1757.56
A24: R34.2 U1.K13 | length 1689.1
  Top Layer w5: U1.K13@1658.76,2057.98 1658.76,2084.76 1864,2290 2426,2290 2471,2245 2471,1616.92 v1(2411.64,1557.56)
  Bottom Layer w20: v1(2411.64,1557.56) R34.2@2446.04,1557.56
A24_1: J4.24 R34.1 | length 82
  Bottom Layer w15: R34.1@2482.04,1557.56 J4.24@2564.04,1557.56
A25: pad.@1711.69,1690.09 R35.2 U1.L4 | length 949.6
  Top Layer w22: U1.L4@1698.13,1703.65 pad.@1711.69,1690.09
  INT1 w5: pad.@1711.69,1690.09 1671,1649.39 1671,1618 1756,1533 1827.08,1533 1848.08,1512 2357.2,1512 v1(2411.64,1457.56)
  Bottom Layer w20: v1(2411.64,1457.56) R35.2@2446.04,1457.56
A25_1: J4.26 R35.1 | length 82
  Bottom Layer w15: R35.1@2482.04,1457.56 J4.26@2564.04,1457.56
A26: R36.2 U1.M2 | length 819.3
  Top Layer w5: U1.M2@1737.5,1624.91 1868.41,1494 2275.2,1494 v1(2411.64,1357.56)
  Bottom Layer w20: v1(2411.64,1357.56) R36.2@2446.04,1357.56
A26_1: J4.28 R36.1 | length 82
  Bottom Layer w15: R36.1@2482.04,1357.56 J4.28@2564.04,1357.56
A27: R37.2 | length 34.4
  Bottom Layer w20: v1(2411.64,1257.56) R37.2@2446.04,1257.56
A27_1: J4.30 R37.1 | length 82
  Bottom Layer w15: R37.1@2482.04,1257.56 J4.30@2564.04,1257.56
ADC_B: J8.34 U8.12 | length 3222.3
  Top Layer w5: J8.34@235.69,1057.56 286.13,1108 359,1108 395,1144 395,1277 364,1308 177,1308 105,1380 105,2653 232,2780 912,2780 1080,2948 1080,2990 1108.5,3018.5 v1(1169.84,3018.5)
  Bottom Layer w15: v1(1169.84,3018.5) U8.12@1217.56,3018.5
ADC_CLK: J8.4 U8.11 | length 1401.4
  INT1 w5: J8.4@235.69,2557.56 191,2602.25 191,2695 256,2760 434,2760 591,2917 1040,2917 1116,2993 1265.18,2993 v1(1265.28,2992.91)
  Bottom Layer w15: U8.11@1217.56,2992.91 v1(1265.28,2992.91)
ADC_CN: J8.32 U8.10 | length 3519.1
  Bottom Layer w5: J8.32@235.69,1157.56 286,1207.87 286,1586 265,1607 197,1607 101,1703 101,3041 407,3347 925,3347 1106,3166 1106,2999 1137.68,2967.32 v1(1169.84,2967.32)
  Bottom Layer w15: v1(1169.84,2967.32) U8.10@1217.56,2967.32
ADC_D0: J8.3 U8.13 | length 1469
  Top Layer w5: J8.3@335.69,2557.56 395.56,2557.56 549,2711 913,2711 941,2683 1281,2683 1325,2727 1325,2984 1359.5,3018.5 v1(1392.28,3018.5)
  Bottom Layer w15: v1(1392.28,3018.5) U8.13@1440,3018.5
ADC_D1: J8.5 U8.14 | length 1584
  Top Layer w5: J8.5@335.69,2457.56 485.13,2607 729,2607 794,2672 917,2672 931.44,2657.56 1294.56,2657.56 1349,2712 1349,2969 1372.91,2992.91 v1(1487.72,2992.91)
  Bottom Layer w15: U8.14@1440,2992.91 v1(1487.72,2992.91)
ADC_D2: J8.7 U8.15 | length 1565.2
  Top Layer w5: J8.7@335.69,2357.56 487.13,2509 715,2509 759,2553 759,2601 807,2649 910,2649 926,2633 1305,2633 1419.17,2747.17 1419.17,2940.43 v1(1392.28,2967.32)
  Bottom Layer w15: v1(1392.28,2967.32) U8.15@1440,2967.32
ADC_D3: J8.9 U8.16 | length 1620.8
  Top Layer w5: J8.9@335.69,2257.56 396.56,2257.56 546,2407 721,2407 745,2431 745,2503 808,2566 907,2566 949,2608 1317,2608 1440,2731 1440,2894.01 v1(1487.72,2941.72)
  Bottom Layer w15: U8.16@1440,2941.72 v1(1487.72,2941.72)
ADC_D4: J8.13 U8.17 | length 1807.4
  INT1 w5: J8.13@335.69,2057.56 459,2180.87 459,2596 574,2711 1079,2711 1113,2677 1283,2677 1313,2707 1313,2836.85 v1(1392.28,2916.13)
  Bottom Layer w15: v1(1392.28,2916.13) U8.17@1440,2916.13
ADC_D5: J8.15 U8.18 | length 1929.3
  INT1 w5: J8.15@335.69,1957.56 397,2018.87 397,2079 483,2165 483,2317 573,2407 721,2407 751,2437 751,2636 804,2689 1062,2689 1099,2652 1308,2652 1332,2676 1332,2798.18 1372.82,2839 1436.17,2839 v1(1487.72,2890.54)
  Bottom Layer w15: U8.18@1440,2890.54 v1(1487.72,2890.54)
ADC_D6: J8.17 U8.22 | length 1964.8
  INT1 w5: J8.17@335.69,1857.56 390,1911.87 390,1972 422,2004 422,2061 508,2147 508,2241 574,2307 715,2307 774,2366 774,2625 816,2667 1043,2667 1087,2623 1323,2623 1355,2655 1355,2770.71 1372.47,2788.18 v1(1487.72,2788.18)
  Bottom Layer w15: U8.22@1440,2788.18 v1(1487.72,2788.18)
ADC_D7: J8.19 U8.23 | length 1939.5
  INT1 w5: J8.19@335.69,1757.56 492,1913.87 492,2073 541,2122 541,2190 560,2209 718,2209 797,2288 797,2608 833,2644 1024,2644 1069,2599 1333,2599 1392.28,2658.28 v1(1392.28,2762.59)
  Bottom Layer w15: v1(1392.28,2762.59) U8.23@1440,2762.59
ADC_D8: J8.6 U8.24 | length 1846.1
  INT1 w5: J8.6@235.69,2457.56 285,2506.87 285,2705 311,2731 443,2731 533,2821 908,2821 957,2870 1187,2870 1234,2917 1317,2917 1343,2943 1438,2943 1463,2918 1501,2918 1524,2895 1524,2773.28 v1(1487.72,2737)
  Bottom Layer w15: U8.24@1440,2737 v1(1487.72,2737)
ADC_D9: J8.8 U8.1 | length 1463.8
  INT1 w5: J8.8@235.69,2357.56 285.13,2407 367,2407 384,2424 384,2635 540,2791 920,2791 975,2846 1182.64,2846 1233.64,2795 1233.64,2768.64 v1(1265.28,2737)
  Bottom Layer w15: U8.1@1217.56,2737 v1(1265.28,2737)
ADC_D10: J8.10 U8.2 | length 1348.6
  INT1 w5: J8.10@235.69,2257.56 285.13,2307 363,2307 411,2355 411,2624 549.59,2762.59 v1(1169.84,2762.59)
  Bottom Layer w15: v1(1169.84,2762.59) U8.2@1217.56,2762.59
ADC_D11: J8.18 U8.3 | length 1935.7
  INT1 w5: J8.18@235.69,1857.56 285,1906.87 285,2190 304,2209 370,2209 433,2272 433,2607 558,2732 1094,2732 1127,2699 1278,2699 1294,2715 1294,2759.46 v1(1265.28,2788.18)
  Bottom Layer w15: U8.3@1217.56,2788.18 v1(1265.28,2788.18)
ADC_IN: J1.5 J1.6 J1.7 J1.8 U8.6 | length 1330.2
  Top Layer w20: J1.8@380,2907 J1.7@380,3007 J1.6@380,3107 J1.5@380,3207
  Bottom Layer w5: J1.6@380,3107 430,3157 537,3157 602,3092 602,3005 700,2907 1091,2907 1133.05,2864.95 U8.6@1217.56,2864.95
ADC_REF: U8.5 U9.6 | length 650.9
  Bottom Layer w5: U8.5@1217.56,2839.36 1296.64,2839.36 1331,2805 1331,2731 1369,2693 1551,2693 1584,2726 1584,2787 1610,2813 U9.6@1679,2813
AMON: J1.1 pad.@1580.02,1605.73 U1.H2 | length 2677.7
  Top Layer w22: pad.@1580.02,1605.73 U1.H2@1580.02,1624.91
  INT1 w5: J1.1@480,3207 1079,3207 1164,3122 1442,3122 1589,2975 1589,2687 1653,2623 1653,1982 1617,1946 1617,1838 1586,1807 1586,1758 1547,1719 1547,1638.74 pad.@1580.02,1605.73
C_SENSE: J1.4 U13.9 | length 1611
  Bottom Layer w5: J1.4@480,2907 594,2793 958,2793 1095.57,2655.43 U13.9@1986.83,2655.43
CR#: pad.@1619.39,1605.73 R8.2 U1.J2 | length 1507.6
  Top Layer w22: pad.@1619.39,1605.73 U1.J2@1619.39,1624.91
  INT1 w5: pad.@1619.39,1605.73 1619.39,1545.61 1727,1438 2174,1438 2406,1206 2762.27,1206 v1(2840.31,1127.96)
  Bottom Layer w20: R8.2@2840.31,1093.56 v1(2840.31,1127.96)
CR#_1: J3.34 R8.1 | length 82
  Bottom Layer w15: R8.1@2840.31,1057.56 J3.34@2922.31,1057.56
DMON: J8.16 pad.@1540.65,1605.73 U1.G2 | length 1591.6
  Top Layer w22: pad.@1540.65,1605.73 U1.G2@1540.65,1624.91
  Bottom Layer w5: J8.16@235.69,1957.56 283.25,1910 380,1910 390,1900 889,1900 1287,1502 1498,1502 1540.65,1544.65 pad.@1540.65,1605.73
DQ0: DQ0.1 pad.@1363.98,1664.28 R38.2 R70.2 U1.C3 | length 2996.3
  Top Layer w5: DQ0.1@-26,2935 66,2935 167,2834 514,2834 547,2867 v1(547,2935.6)
  Top Layer w22: pad.@1363.98,1664.28 U1.C3@1383.17,1664.28
  Bottom Layer w5: 545,2958 451,2958 429,2936 429,2808 475.92,2761.08 R38.2@475.92,2505.12 473.92,2505.12 402,2433.2 402,1945 431,1916 901,1916 1152.72,1664.28 pad.@1363.98,1664.28
  Bottom Layer w20: v1(547,2935.6) R70.2@547,2970
DQ0_1: J6.3 R38.1 | length 203.8
  Bottom Layer w5: R38.1@511.92,2505.12 605.12,2505.12 657.56,2557.56 J6.3@693.96,2557.56
DQ0_P: J1.3 R70.1 | length 68.4
  Bottom Layer w15: J1.3@480,3007 480.5,3006.5 546.5,3006.5 547,3007 R70.1@547,3006
DQ1: pad.@1408.97,1729.46 R39.2 U1.D5 | length 1463.2
  Top Layer w22: pad.@1408.97,1729.46 U1.D5@1422.54,1743.02
  Bottom Layer w5: R39.2@475.92,2405.12 473.92,2405.12 466.42,2397.62 466.42,2395.62 440,2369.2 440,2104 543,2001 1014,2001 1291,1724 1379,1724 pad.@1408.97,1729.46
DQ1_1: J6.5 R39.1 | length 203.8
  Bottom Layer w5: R39.1@511.92,2405.12 608.12,2405.12 660.56,2457.56 J6.5@693.96,2457.56
DQ2: pad.@1363.98,1743.02 R40.2 U1.C5 | length 1262.5
  Top Layer w22: pad.@1363.98,1743.02 U1.C5@1383.17,1743.02
  Bottom Layer w5: R40.2@475.92,2305.12 475.92,2096.08 555,2017 1025,2017 1298.98,1743.02 pad.@1363.98,1743.02
DQ2_1: J6.7 R40.1 | length 203.8
  Bottom Layer w5: R40.1@511.92,2305.12 607.12,2305.12 659.56,2357.56 J6.7@693.96,2357.56
DQ3: pad.@1448.34,1808.2 R41.2 U1.E7 | length 898.9
  Top Layer w22: pad.@1448.34,1808.2 U1.E7@1461.91,1821.76
  Bottom Layer w5: R41.2@811.96,2257.56 875.44,2257.56 1221,1912 1413,1912 1469,1856 1469,1828.86 pad.@1448.34,1808.2
DQ3_1: J6.9 R41.1 | length 82
  Bottom Layer w15: J6.9@693.96,2257.56 R41.1@775.96,2257.56
DQ4: pad.@1408.97,1886.94 R42.2 U1.D9 | length 686.9
  Top Layer w22: pad.@1408.97,1886.94 U1.D9@1422.54,1900.5
  Bottom Layer w5: R42.2@811.96,2057.56 1049.44,2057.56 1220.06,1886.94 pad.@1408.97,1886.94
DQ4_1: J6.13 R42.1 | length 82
  Bottom Layer w15: J6.13@693.96,2057.56 R42.1@775.96,2057.56
DQ5: R43.2 U1.D11 | length 635.9
  Top Layer w5: v1(846.36,1957.56) 1307.56,1957.56 1349,1999 1402.78,1999 U1.D11@1422.54,1979.24
  Bottom Layer w20: R43.2@811.96,1957.56 v1(846.36,1957.56)
DQ5_1: J6.15 R43.1 | length 82
  Bottom Layer w15: J6.15@693.96,1957.56 R43.1@775.96,1957.56
DQ6: R44.2 U1.C12 | length 761.1
  Top Layer w5: v1(846.36,1857.56) 805,1898.92 805,1968 827,1990 1315,1990 1343.61,2018.61 U1.C12@1383.17,2018.61
  Bottom Layer w20: R44.2@811.96,1857.56 v1(846.36,1857.56)
DQ6_1: J6.17 R44.1 | length 82
  Bottom Layer w15: J6.17@693.96,1857.56 R44.1@775.96,1857.56
DQ7: R45.2 U1.G12 | length 1937.2
  Top Layer w5: v1(846.36,1757.56) 795.44,1757.56 748,1805 542,1805 408,1939 408,1982 534,2108 752,2108 831,2187 1473,2187 1521,2139 1521,2038.26 U1.G12@1540.65,2018.61
  Bottom Layer w20: R45.2@811.96,1757.56 v1(846.36,1757.56)
DQ7_1: J6.19 R45.1 | length 82
  Bottom Layer w15: J6.19@693.96,1757.56 R45.1@775.96,1757.56
DQ8: R46.2 U1.D4 | length 1599.3
  Top Layer w5: v1(441.52,1610) 441.52,1546.52 388,1493 388,1362 443,1307 721,1307 798,1230 865,1230 1199,1564 1199,1580 1303,1684 1402.88,1684 U1.D4@1422.54,1703.65
  Bottom Layer w20: v1(441.52,1610) R46.2@475.92,1610
DQ8_1: J6.23 R46.1 | length 203.8
  Bottom Layer w5: R46.1@511.92,1610 536,1610 548,1598 615,1598 655.44,1557.56 J6.23@693.96,1557.56
DQ9: R47.2 U1.D6 | length 756.3
  Top Layer w5: v1(847.4,1428) 890,1428 1225,1763 1403.14,1763 U1.D6@1422.54,1782.39
  Bottom Layer w20: R47.2@813,1428 v1(847.4,1428)
DQ9_1: J6.25 R47.1 | length 95.3
  Bottom Layer w15: J6.25@693.96,1457.56 723.52,1428 R47.1@777,1428
DQ10: R48.2 U1.C6 | length 846.8
  Top Layer w5: v1(846.36,1357.56) 813,1390.92 813,1447 831,1465 888,1465 1205.39,1782.39 U1.C6@1383.17,1782.39
  Bottom Layer w20: R48.2@811.96,1357.56 v1(846.36,1357.56)
DQ10_1: J6.27 R48.1 | length 82
  Bottom Layer w15: J6.27@693.96,1357.56 R48.1@775.96,1357.56
DQ11: R49.2 U1.C8 | length 1049.3
  Top Layer w5: v1(846.36,1257.56) 788,1315.92 788,1506 828,1546 893,1546 1208.13,1861.13 U1.C8@1383.17,1861.13
  Bottom Layer w20: R49.2@811.96,1257.56 v1(846.36,1257.56)
DQ11_1: J6.29 R49.1 | length 82
  Bottom Layer w15: J6.29@693.96,1257.56 R49.1@775.96,1257.56
DQ12: pad.@1487.71,1914.07 R50.2 U1.F9 | length 1823
  Top Layer w22: pad.@1487.71,1914.07 U1.F9@1501.28,1900.5
  INT1 w5: v1(846.36,1057.56) 885,1096.2 885,1541 770,1656 770,1932 832,1994 1316,1994 1334,2012 1458,2012 1467.78,2002.22 1467.78,1934 pad.@1487.71,1914.07
  Bottom Layer w20: R50.2@811.96,1057.56 v1(846.36,1057.56)
DQ12_1: J6.33 R50.1 | length 82
  Bottom Layer w15: J6.33@693.96,1057.56 R50.1@775.96,1057.56
DQ13: pad.@1448.34,1953.44 R51.2 U1.E10 | length 1740.6
  Top Layer w22: pad.@1448.34,1953.44 U1.E10@1461.91,1939.87
  INT1 w5: v1(846.36,957.56) 913,1024.2 913,1543 794,1662 794,1885 825,1916 1389,1916 1426.44,1953.44 pad.@1448.34,1953.44
  Bottom Layer w20: R51.2@811.96,957.56 v1(846.36,957.56)
DQ13_1: J6.35 R51.1 | length 82
  Bottom Layer w15: J6.35@693.96,957.56 R51.1@775.96,957.56
DQ14: pad.@1527.08,1992.81 R52.2 U1.G11 | length 2295.2
  Top Layer w22: pad.@1527.08,1992.81 U1.G11@1540.65,1979.24
  INT1 w5: v1(441.52,910) 411,940.52 411,1279 481,1349 481,1737 549,1805 619,1805 643,1829 643,1992 659,2008 776,2008 808,2040 1207,2040 1252,2085 1416,2085 1432,2101 1480,2101 1527.08,2053.92 pad.@1527.08,1992.81
  Bottom Layer w20: v1(441.52,910) R52.2@475.92,910
DQ14_1: J6.37 R52.1 | length 203.8
  Bottom Layer w5: R52.1@511.92,910 641.52,910 J6.37@693.96,857.56
DQ15: pad.@1461.91,2077.17 R53.2 U1.E13 | length 2189.5
  Top Layer w22: U1.E13@1461.91,2057.98 pad.@1461.91,2077.17
  INT1 w5: v1(846.36,757.56) 942,853.2 942,1546 819,1669 819,1872 842,1895 1318,1895 1346,1867 1477,1867 1507,1897 1507,2050 1479.83,2077.17 pad.@1461.91,2077.17
  Bottom Layer w20: R53.2@811.96,757.56 v1(846.36,757.56)
DQ15_1: J6.39 R53.1 | length 82
  Bottom Layer w15: J6.39@693.96,757.56 R53.1@775.96,757.56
